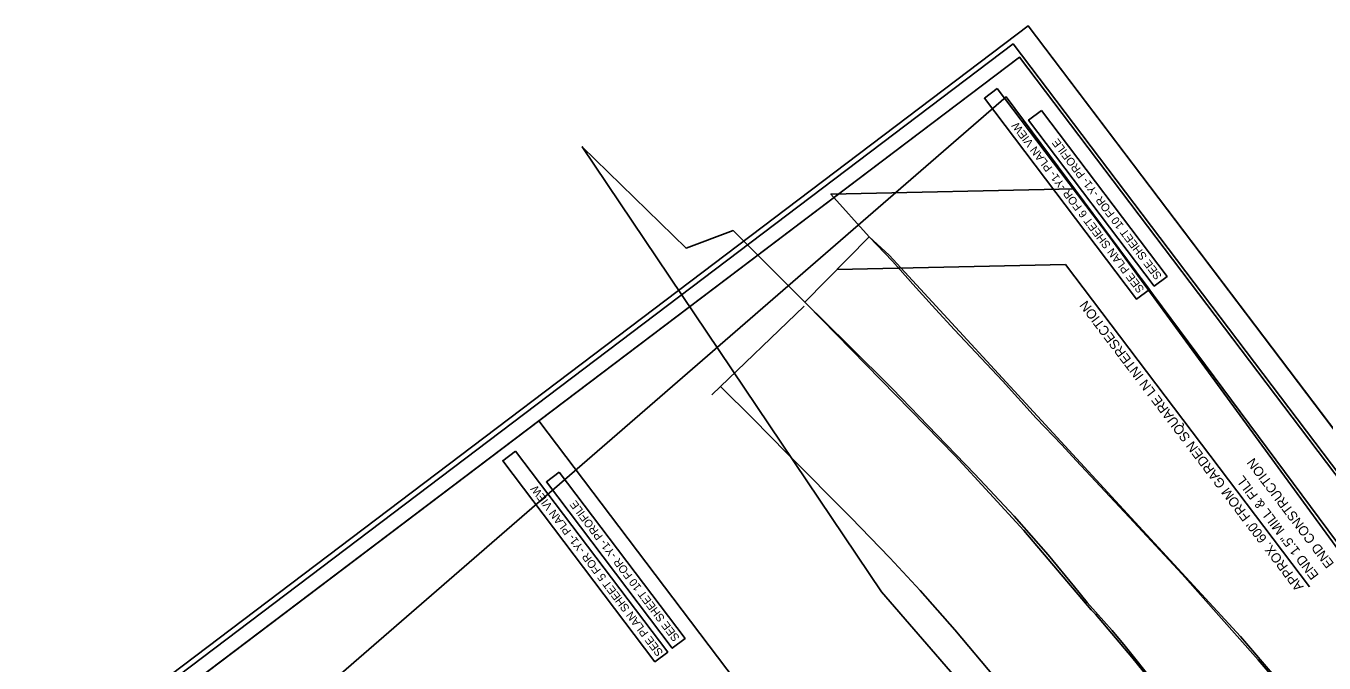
# Model space of a CAD drawing. Extents: x 2046295 to 2051060, y 758814 to 763808.
# Drawn here: x 2046295 to 2046974, y 759682 to 760015 of the extents above; entities that cross this region are included whole.
import ezdxf

# ---------------------------------------------------------------- set-up
doc = ezdxf.new("R2010")
doc.units = 0
for name, color, linetype in [('Prop DSN Text', 7, 'Continuous'), ('Prop EOT', 7, 'Continuous'), ('Prop Grid Mask', 7, 'Continuous'), ('Scratch_Level_0', 7, 'Continuous'), ('Sheet Block Revision CELL', 7, 'Continuous'), ('Sheet Clip Boundary CELL', 7, 'Continuous'), ('Sheet Cutting Line CELL', 7, 'Continuous'), ('Sheet Plan CELL', 7, 'Continuous'), ('Sheet Plot Border Inside CELL', 7, 'Continuous'), ('Sheet Plot Border Outside CELL', 7, 'Continuous')]:
    doc.layers.add(name, color=color, linetype=linetype)

msp = doc.modelspace()

# ---------------------------------------------------------------- linework, layer by layer
at = {"layer": 'Prop DSN Text'}
msp.add_line((2046653.63, 759822.64), (2046701.84, 759868.98), dxfattribs=at)
for points in [[(2046719.12, 759888.16), (2046838.42, 759890.75), (2046965.93, 759722.33)], [(2046692.83, 759792.18), (2046675.27, 759810.07), (2046658.25, 759827.08)], [(2046801.8, 759674.76), (2046780.7, 759699.83), (2046762.53, 759720.33), (2046746.64, 759737.54), (2046726.23, 759758.63), (2046693.13, 759791.87)]]:
    msp.add_lwpolyline(points, dxfattribs=at)
msp.add_arc((2046736.05, 759834.61), 60.56, 224.47401, 224.88003, dxfattribs=at)
at = {"layer": 'Prop EOT'}
for p, q in [((2046702.29, 759871.09), (2046735.95, 759905.24)), ((2046725.11, 759848.59), (2046702.29, 759871.09))]:
    msp.add_line(p, q, dxfattribs=at)
for points in [[(2047095.91, 759487.83), (2047060.1, 759534.55), (2047037.66, 759563.83), (2047019.89, 759587.02), (2047003.2, 759607.99), (2046976.38, 759640.27), (2046961.44, 759658.24), (2046939.14, 759684.21), (2046899.4, 759728.85), (2046871.69, 759758.79), (2046844.06, 759788.42), (2046836.53, 759796.51), (2046823.09, 759810.56), (2046805.62, 759829.99), (2046780.45, 759856.59), (2046770.6, 759867.45), (2046758.76, 759880.49), (2046748.01, 759892.54), (2046735.95, 759905.24)], [(2046829.52, 759739.07), (2046811.61, 759759.31), (2046791.08, 759781.16), (2046771.24, 759801.81), (2046748.03, 759825.79), (2046725.11, 759848.59)], [(2047051.48, 759453.65), (2047026.19, 759487.57), (2047004.02, 759517.31), (2046975.49, 759555.05), (2046969.9, 759562.91), (2046958.31, 759578.45), (2046946.96, 759593.22), (2046930.3, 759614.91), (2046923.02, 759624.38), (2046916.39, 759632.65), (2046910.23, 759640.6), (2046901.22, 759651.47), (2046884.87, 759672.25), (2046869.65, 759691.35), (2046862.8, 759699.47), (2046849.9, 759714.08), (2046843.12, 759722.39), (2046829.52, 759739.07)]]:
    msp.add_lwpolyline(points, dxfattribs=at)
at = {"layer": 'Prop Grid Mask'}
for points in [[(2046802.78, 759982.74), (2046882.32, 759877.69), (2046875.63, 759872.63), (2046796.1, 759977.68)], [(2046825.89, 759971.32), (2046891.56, 759884.57), (2046884.88, 759879.51), (2046819.2, 759966.25)], [(2046551.06, 759793.29), (2046630.59, 759688.24), (2046623.9, 759683.17), (2046544.37, 759788.22)], [(2046573.91, 759782.2), (2046639.7, 759695.31), (2046633.01, 759690.24), (2046567.22, 759777.14)]]:
    msp.add_lwpolyline(points, close=True, dxfattribs=at)
at = {"layer": 'Scratch_Level_0'}
for points in [[(2047115.74, 759268.55), (2046954.25, 759474.97), (2046742.37, 759719.71), (2046585.96, 759952.37), (2046640.17, 759899.32), (2046664.8, 759908.52), (2046703.35, 759870.04), (2046780.77, 759790.76), (2046816.65, 759751.71), (2046851.83, 759710.23), (2046854.21, 759708.09), (2046873.14, 759685.6), (2046930.3, 759614.91), (2047005.4, 759513.5)], [(2046984.79, 759632.17), (2046929.97, 759696.38), (2046746.39, 759895.6), (2046735.95, 759905.24), (2046715.87, 759927.6), (2046843.22, 759930.29), (2047114.24, 759559.33)]]:
    msp.add_lwpolyline(points, dxfattribs=at)
at = {"layer": 'Sheet Block Revision CELL'}
msp.add_line((2047106.56, 759091.51), (2046563.3, 759809.07), dxfattribs=at)
at = {"layer": 'Sheet Clip Boundary CELL'}
msp.add_lwpolyline([(2046947.67, 758972.8), (2047186.85, 759153.88), (2047203.68, 759209.07), (2047315.83, 759293.98), (2046807.51, 759978.36), (2046429.78, 759650.86), (2046498.33, 759560.32), (2046397.16, 759483.72), (2046835.66, 758904.54)], close=True, dxfattribs=at)
at = {"layer": 'Sheet Cutting Line CELL'}
msp.add_line((2047428.76, 759210.16), (2046819.05, 760015.49), dxfattribs=at)
at = {"layer": 'Sheet Plan CELL'}
for points in [[(2046312.14, 759618.94), (2046855.41, 758901.37), (2047357.69, 759281.65), (2046814.43, 759999.2)], [(2047357.69, 759281.65), (2046855.43, 758901.37), (2046384.6, 759523.22), (2046456.38, 759577.58), (2046383.94, 759673.27), (2046814.43, 759999.2)]]:
    msp.add_lwpolyline(points, close=True, dxfattribs=at)
at = {"layer": 'Sheet Plot Border Inside CELL'}
msp.add_lwpolyline([(2047414.48, 759209.14), (2046811.11, 760006.08), (2046306.43, 759624), (2046909.81, 758827.05)], close=True, dxfattribs=at)
at = {"layer": 'Sheet Plot Border Outside CELL'}
msp.add_lwpolyline([(2047428.76, 759210.16), (2046819.05, 760015.49), (2046295.24, 759618.91), (2046904.95, 758813.59)], close=True, dxfattribs=at)

# ---------------------------------------------------------------- texts
at = {"layer": 'Prop DSN Text'}
for s, p in [("APPROX. 600' FROM GARDEN SQUARE LN INTERSECTION", (2046963.1, 759722.4)), ('END CONSTRUCTION', (2046979.05, 759734.47)), ('END 1.5" MILL & FILL', (2046971.07, 759728.43))]:
    msp.add_text(s, height=5, rotation=127.12988, dxfattribs=at).set_placement(p)
at = {"layer": 'Prop Grid Mask'}
for s, p in [('SEE PLAN SHEET 6 FOR -Y1- PLAN VIEW', (2046879.9, 759877.87)), ('SEE SHEET 10 FOR -Y1- PROFILE', (2046889.08, 759884.85)), ('SEE PLAN SHEET 5 FOR -Y1- PLAN VIEW', (2046628.49, 759688)), ('SEE SHEET 10 FOR -Y1- PROFILE', (2046637.09, 759695.74))]:
    msp.add_text(s, height=4.2, rotation=127.12944, dxfattribs=at).set_placement(p)

doc.saveas('drawing.dxf')
